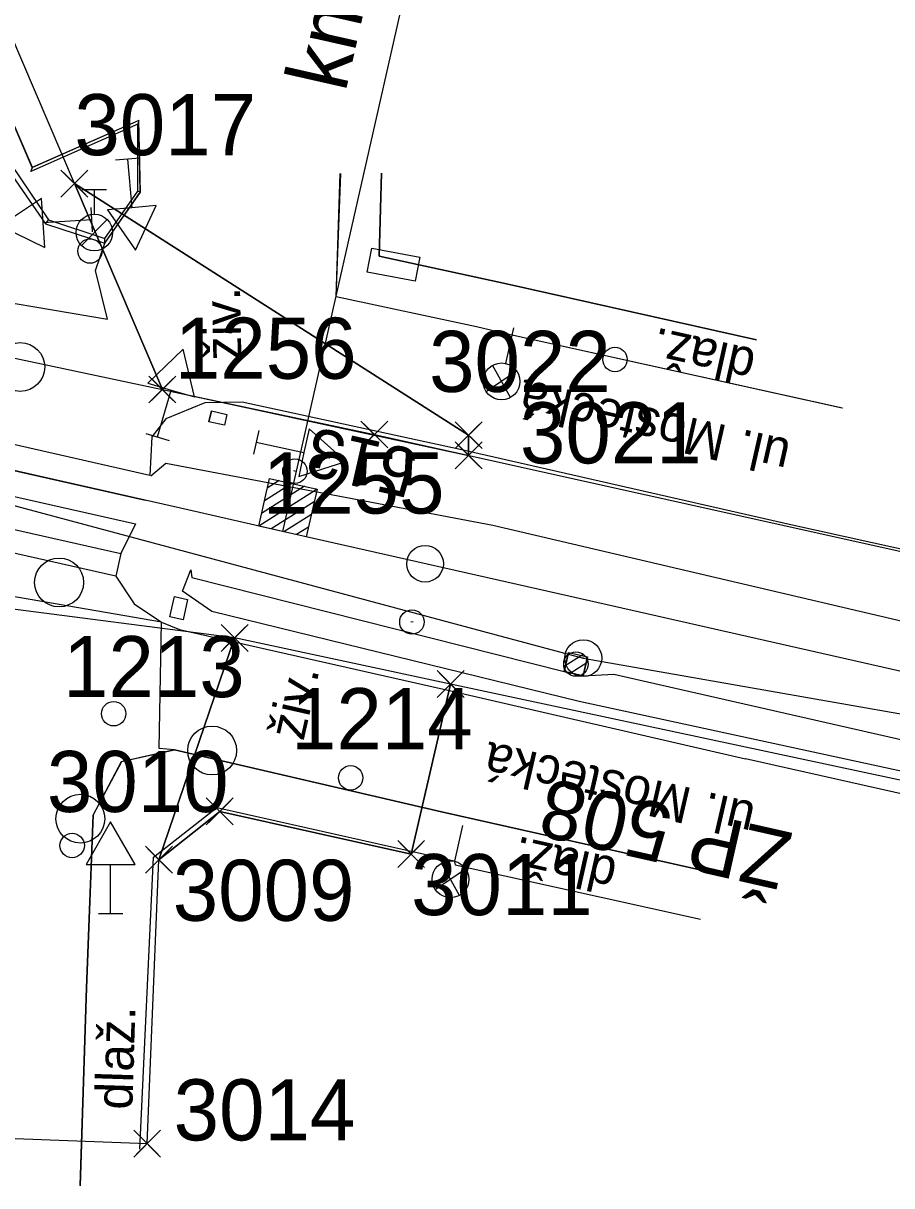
# Model space of a CAD drawing. Extents: x -738085 to -734426, y -1122197 to -1119748.
# Drawn here: x -734690.39 to -734654.84, y -1120232.59 to -1120185 of the extents above; entities that cross this region are included whole.
import ezdxf

# ---------------------------------------------------------------- set-up
doc = ezdxf.new("R2010")
doc.units = 0
for name, color, linetype in [('Dočasný zábor - do 1 roku', 7, 'Continuous'), ('SŽDC', 7, 'Continuous'), ('Vrstva 1', 7, 'Continuous'), ('Vrstva 11', 7, 'Continuous'), ('Vrstva 12', 7, 'Continuous'), ('Vrstva 16', 7, 'Continuous'), ('Vrstva 17', 7, 'Continuous'), ('Vrstva 23', 7, 'Continuous'), ('Vrstva 25', 7, 'Continuous'), ('Vrstva 27', 7, 'Continuous'), ('Vrstva 3', 7, 'Continuous'), ('Vrstva 4', 7, 'Continuous'), ('Vrstva 41', 7, 'Continuous'), ('Vrstva 43', 7, 'Continuous'), ('Vrstva 47', 7, 'Continuous'), ('Vrstva 49', 7, 'Continuous'), ('Vrstva 51', 7, 'Continuous'), ('Vrstva 60', 7, 'Continuous'), ('Vrstva 63', 7, 'Continuous'), ('Vrstva 7', 7, 'Continuous')]:
    doc.layers.add(name, color=color, linetype=linetype)

msp = doc.modelspace()

# ---------------------------------------------------------------- linework, layer by layer
at = {"layer": 'Dočasný zábor - do 1 roku'}
for p, q in [((-734688.3, -1120191.56), (-734697.213, -1120170.677)), ((-734684.7, -1120199.99), (-734688.3, -1120191.56)), ((-734688.3, -1120191.56), (-734684.7, -1120199.99)), ((-734672.163, -1120201.858), (-734688.3, -1120191.56)), ((-734700.75, -1120196.59), (-734684.7, -1120199.99)), ((-734684.7, -1120199.99), (-734672.163, -1120202.687)), ((-734672.163, -1120202.687), (-734672.163, -1120201.858)), ((-734681.74, -1120210.16), (-734699.68, -1120207.84)), ((-734684.84, -1120219.24), (-734681.74, -1120210.16)), ((-734672.9, -1120212.048), (-734681.74, -1120210.16)), ((-734681.74, -1120210.16), (-734681.74, -1120210.16)), ((-734674.515, -1120219.007), (-734672.9, -1120212.048)), ((-734685.32, -1120230.86), (-734684.84, -1120219.24)), ((-734700.26, -1120230.299), (-734685.32, -1120230.86))]:
    msp.add_line(p, q, dxfattribs=at)
for points in [[(-734688.3, -1120191.56), (-734672.163, -1120201.858), (-734672.163, -1120202.687)], [(-734681.74, -1120210.16), (-734684.84, -1120219.24), (-734682.35, -1120217.26), (-734674.515, -1120219.007)], [(-734672.9, -1120212.048), (-734674.515, -1120219.007), (-734682.35, -1120217.26), (-734684.84, -1120219.24)]]:
    msp.add_lwpolyline(points, dxfattribs=at)
at = {"layer": 'SŽDC'}
for p, q in [((-734700.75, -1120196.59), (-734684.7, -1120199.99)), ((-734684.7, -1120199.99), (-734676.02, -1120201.83)), ((-734676.02, -1120201.83), (-734595.59, -1120219.69)), ((-734681.74, -1120210.16), (-734699.68, -1120207.84))]:
    msp.add_line(p, q, dxfattribs=at)
msp.add_lwpolyline([(-734644.28, -1120218.16), (-734672.9, -1120212.048), (-734681.74, -1120210.16)], dxfattribs=at)
at = {"layer": 'Vrstva 1'}
msp.add_lwpolyline([(-734613.421, -1120220.79), (-734634.887, -1120215.956), (-734653.902, -1120211.657), (-734667.211, -1120208.647), (-734679.781, -1120205.8), (-734683.652, -1120204.918), (-734685.399, -1120204.523), (-734700.124, -1120201.196), (-734707.734, -1120199.476), (-734730.994, -1120194.203), (-734759.473, -1120187.753), (-734794.897, -1120179.749), (-734825.419, -1120172.844), (-734846.465, -1120168.091), (-734858.476, -1120165.343)], dxfattribs=at)
msp.add_lwpolyline([(-734613.421, -1120220.79), (-734634.887, -1120215.956), (-734653.902, -1120211.657), (-734667.211, -1120208.647), (-734679.781, -1120205.8), (-734683.652, -1120204.918), (-734685.399, -1120204.523), (-734700.124, -1120201.196), (-734707.734, -1120199.476), (-734730.994, -1120194.203), (-734759.473, -1120187.753), (-734794.897, -1120179.749), (-734825.419, -1120172.844), (-734846.465, -1120168.091), (-734858.476, -1120165.343)], dxfattribs=at)
at = {"layer": 'Vrstva 11'}
for p, q in [((-734667.473, -1120210.832), (-734668.256, -1120211.326)), ((-734667.279, -1120211.152), (-734668.051, -1120211.64))]:
    msp.add_line(p, q, dxfattribs=at)
msp.add_circle((-734667.769, -1120211.23), 0.5, dxfattribs=at)
at = {"layer": 'Vrstva 12'}
for p, q in [((-734682.692, -1120200.869), (-734682.792, -1120201.308)), ((-734682.058, -1120201.012), (-734682.158, -1120201.451)), ((-734667.467, -1120211.708), (-734667.291, -1120210.928))]:
    msp.add_line(p, q, dxfattribs=at)
for points in [[(-734682.158, -1120201.451), (-734682.792, -1120201.308), (-734682.692, -1120200.869), (-734682.058, -1120201.012), (-734682.158, -1120201.451)], [(-734682.692, -1120200.869), (-734682.692, -1120200.869), (-734682.058, -1120201.012), (-734682.058, -1120201.012)], [(-734684.2, -1120208.469), (-734683.664, -1120208.591), (-734683.852, -1120209.42), (-734684.389, -1120209.297), (-734684.2, -1120208.469)], [(-734668.071, -1120210.752), (-734667.291, -1120210.928), (-734667.467, -1120211.708), (-734668.248, -1120211.532), (-734668.071, -1120210.752)], [(-734668.071, -1120210.752), (-734668.248, -1120211.532), (-734668.248, -1120211.532)], [(-734668.248, -1120211.532), (-734667.467, -1120211.708), (-734667.467, -1120211.708)]]:
    msp.add_lwpolyline(points, dxfattribs=at)
at = {"layer": 'Vrstva 16'}
for p, q in [((-734690.085, -1120191.06), (-734690.021, -1120190.906)), ((-734689.481, -1120193.204), (-734689.48, -1120193.207)), ((-734689.48, -1120193.207), (-734689.361, -1120193.039)), ((-734687.051, -1120194.004), (-734687.053, -1120193.814)), ((-734687.051, -1120194.004), (-734687.051, -1120194.004))]:
    msp.add_line(p, q, dxfattribs=at)
for points in [[(-734693.983, -1120184.429), (-734693.706, -1120184.991), (-734691.09, -1120190.87), (-734689.481, -1120193.204), (-734687.051, -1120194.004), (-734685.594, -1120191.915), (-734685.657, -1120188.975), (-734690.021, -1120190.906), (-734692.007, -1120186.315), (-734692.012, -1120183.607), (-734691.887, -1120180.057), (-734691.681, -1120177.463)], [(-734693.983, -1120184.429), (-734693.673, -1120185.028), (-734691.091, -1120190.868), (-734689.48, -1120193.207), (-734687.051, -1120194.004), (-734685.605, -1120191.915), (-734685.658, -1120188.976), (-734690.023, -1120190.9), (-734692.008, -1120186.313), (-734692.012, -1120183.607)], [(-734693.983, -1120184.429), (-734693.738, -1120184.328), (-734693.487, -1120184.951), (-734690.892, -1120190.781), (-734689.361, -1120193.039), (-734687.053, -1120193.814), (-734685.709, -1120191.874), (-734685.703, -1120189.123), (-734690.085, -1120191.06)], [(-734685.657, -1120188.975), (-734685.658, -1120188.976), (-734685.703, -1120189.123)], [(-734690.021, -1120190.906), (-734690.023, -1120190.9), (-734690.085, -1120191.06)], [(-734656.869, -1120200.755), (-734670.691, -1120197.691), (-734671.842, -1120197.428), (-734677.579, -1120196.192), (-734677.39, -1120191.145)], [(-734675.732, -1120191.133), (-734675.819, -1120194.533), (-734670.613, -1120195.666), (-734660.375, -1120197.952)], [(-734685.594, -1120191.915), (-734685.605, -1120191.915), (-734685.709, -1120191.874)], [(-734662.447, -1120219.703), (-734673.267, -1120217.272), (-734684.199, -1120214.747), (-734686.375, -1120215.227), (-734687.529, -1120217.4), (-734687.799, -1120224.482), (-734688.058, -1120232.586)], [(-734685.615, -1120231.094), (-734685.057, -1120219.13), (-734682.464, -1120217.097), (-734672.751, -1120219.278), (-734672.712, -1120219.442), (-734662.672, -1120221.679)]]:
    msp.add_lwpolyline(points, dxfattribs=at)
at = {"layer": 'Vrstva 17'}
for p, q in [((-734675.819, -1120194.533), (-734675.732, -1120191.133)), ((-734670.613, -1120195.666), (-734675.819, -1120194.533)), ((-734672.712, -1120219.442), (-734662.672, -1120221.679))]:
    msp.add_line(p, q, dxfattribs=at)
at = {"layer": 'Vrstva 23'}
msp.add_line((-734660.375, -1120197.952), (-734670.613, -1120195.666), dxfattribs=at)
msp.add_lwpolyline([(-734685.615, -1120231.094), (-734685.057, -1120219.13), (-734682.464, -1120217.097), (-734672.751, -1120219.278)], dxfattribs=at)
at = {"layer": 'Vrstva 25'}
for p, q in [((-734670.644, -1120198.922), (-734670.313, -1120197.459)), ((-734670.452, -1120200.318), (-734671.18, -1120198.998)), ((-734671.438, -1120200.078), (-734670.196, -1120199.223)), ((-734672.732, -1120219.305), (-734672.401, -1120217.842)), ((-734673.526, -1120220.461), (-734672.284, -1120219.606)), ((-734672.54, -1120220.701), (-734673.268, -1120219.381))]:
    msp.add_line(p, q, dxfattribs=at)
msp.add_lwpolyline([(-734676.308, -1120195.184), (-734676.12, -1120194.202), (-734674.156, -1120194.578), (-734674.344, -1120195.56), (-734676.308, -1120195.184)], dxfattribs=at)
for centre in [(-734670.813, -1120199.657), (-734672.901, -1120220.04)]:
    msp.add_circle(centre, 0.754, dxfattribs=at)
at = {"layer": 'Vrstva 27'}
msp.add_line((-734679.222, -1120203.344), (-734679.32, -1120203.322), dxfattribs=at)
msp.add_circle((-734679.271, -1120203.333), 0.5, dxfattribs=at)
at = {"layer": 'Vrstva 3'}
for p, q in [((-734673.222, -1120176.84), (-734679.781, -1120205.8)), ((-734678.881, -1120203.953), (-734680.639, -1120205.062)), ((-734679.399, -1120203.836), (-734680.522, -1120204.544)), ((-734679.916, -1120203.719), (-734680.405, -1120204.027)), ((-734678.364, -1120204.07), (-734680.756, -1120205.579)), ((-734678.481, -1120204.587), (-734680.239, -1120205.696)), ((-734678.598, -1120205.105), (-734679.722, -1120205.813)), ((-734678.715, -1120205.622), (-734679.205, -1120205.931))]:
    msp.add_line(p, q, dxfattribs=at)
msp.add_lwpolyline([(-734678.806, -1120206.021), (-734680.756, -1120205.579), (-734680.315, -1120203.629), (-734678.364, -1120204.07)], close=True, dxfattribs=at)
at = {"layer": 'Vrstva 4'}
msp.add_line((-734700.124, -1120201.196), (-734685.399, -1120204.523), dxfattribs=at)
msp.add_lwpolyline([(-734685.169, -1120203.528), (-734684.555, -1120202.999), (-734671.173, -1120205.544), (-734644.385, -1120211.815), (-734623.222, -1120216.49), (-734603.28, -1120220.93), (-734589.054, -1120222.819), (-734581.933, -1120222.775)], dxfattribs=at)
at = {"layer": 'Vrstva 41'}
for p, q in [((-734687.984, -1120191.806), (-734686.984, -1120191.806)), ((-734687.484, -1120191.806), (-734687.484, -1120192.814)), ((-734688.015, -1120194.096), (-734686.953, -1120193.035))]:
    msp.add_line(p, q, dxfattribs=at)
msp.add_circle((-734687.484, -1120193.564), 0.75, dxfattribs=at)
at = {"layer": 'Vrstva 43'}
msp.add_lwpolyline([(-734700.082, -1120203.618), (-734686.405, -1120206.705), (-734686.606, -1120207.634), (-734700.287, -1120204.546), (-734700.082, -1120203.618)], dxfattribs=at)
for centre in [(-734690.514, -1120199.067), (-734688.927, -1120207.889), (-734682.661, -1120214.769), (-734688.057, -1120217.561)]:
    msp.add_circle(centre, 1, dxfattribs=at)
at = {"layer": 'Vrstva 47'}
for centre in [(-734687.661, -1120194.322), (-734666.17, -1120198.76), (-734686.692, -1120213.263), (-734676.991, -1120215.888), (-734688.393, -1120218.657)]:
    msp.add_circle(centre, 0.5, dxfattribs=at)
at = {"layer": 'Vrstva 49'}
for p, q in [((-734683.88, -1120208.239), (-734683.53, -1120207.371)), ((-734682.667, -1120209.084), (-734683.88, -1120208.239)), ((-734667.641, -1120212.759), (-734682.667, -1120209.084)), ((-734640.39, -1120218.667), (-734667.641, -1120212.759))]:
    msp.add_line(p, q, dxfattribs=at)
msp.add_lwpolyline([(-734683.53, -1120207.371), (-734683.499, -1120207.692), (-734668.248, -1120211.532), (-734667.467, -1120211.708), (-734666.214, -1120211.637), (-734640.018, -1120217.602), (-734614.508, -1120223.672), (-734613.724, -1120223.83), (-734612.931, -1120223.724), (-734598.542, -1120226.335), (-734585.987, -1120228.092), (-734583.653, -1120227.271)], dxfattribs=at)
at = {"layer": 'Vrstva 51'}
for p, q in [((-734685.622, -1120190.513), (-734686.618, -1120190.599)), ((-734687.554, -1120193.538), (-734687.62, -1120192.54)), ((-734687.437, -1120195.122), (-734687.051, -1120194.004)), ((-734697.93, -1120195.257), (-734686.949, -1120197.112)), ((-734686.949, -1120197.112), (-734687.437, -1120195.122)), ((-734685.38, -1120201.792), (-734684.42, -1120202.072)), ((-734680.753, -1120201.662), (-734680.965, -1120202.64)), ((-734687.318, -1120221.439), (-734686.318, -1120221.439))]:
    msp.add_line(p, q, dxfattribs=at)
for points in [[(-734698.706, -1120173.764), (-734695.23, -1120181.618), (-734693.983, -1120184.429), (-734693.706, -1120184.991), (-734691.09, -1120190.87), (-734689.481, -1120193.204), (-734687.051, -1120194.004), (-734685.594, -1120191.915), (-734685.657, -1120188.975)], [(-734685.657, -1120188.975), (-734690.021, -1120190.906), (-734692.007, -1120186.315)], [(-734686.12, -1120190.556), (-734685.947, -1120192.548), (-734686.943, -1120192.635), (-734685.795, -1120194.292), (-734684.95, -1120192.462), (-734685.947, -1120192.548)], [(-734671.842, -1120197.428), (-734677.579, -1120196.192), (-734677.414, -1120191.147)], [(-734687.587, -1120193.039), (-734689.583, -1120193.172), (-734689.649, -1120192.174), (-734691.329, -1120193.288), (-734689.516, -1120194.17), (-734689.583, -1120193.172)], [(-734658.976, -1120205.526), (-734672.503, -1120202.452), (-734681.43, -1120200.503), (-734682.967, -1120200.534), (-734684.561, -1120201.186), (-734685.13, -1120201.924), (-734685.214, -1120203.506), (-734699.559, -1120200.255), (-734700.128, -1120198.059), (-734700.649, -1120196.031), (-734698.09, -1120195.452), (-734697.927, -1120195.313), (-734697.93, -1120195.257), (-734698.04, -1120194.915)], [(-734656.85, -1120200.76), (-734670.693, -1120197.691), (-734671.842, -1120197.428)], [(-734684.9, -1120201.932), (-734684.34, -1120200.012), (-734683.38, -1120200.292), (-734683.85, -1120198.332), (-734685.3, -1120199.732), (-734684.34, -1120200.012)], [(-734680.859, -1120202.151), (-734678.904, -1120202.574), (-734679.115, -1120203.551), (-734677.194, -1120202.943), (-734678.693, -1120201.596), (-734678.904, -1120202.574)], [(-734722.773, -1120203.706), (-734710.677, -1120205.432), (-734705.214, -1120206.089), (-734701.642, -1120204.763), (-734700.144, -1120202.25), (-734685.794, -1120205.483), (-734686.405, -1120206.705), (-734686.606, -1120207.634), (-734685.856, -1120208.767), (-734684.729, -1120209.51), (-734683.999, -1120209.821), (-734673.195, -1120212.261), (-734660.828, -1120215.105)], [(-734581.836, -1120224.609), (-734581.933, -1120222.775), (-734581.75, -1120220.917), (-734582.259, -1120220.314), (-734583.293, -1120219.898), (-734588.526, -1120220.107), (-734595.069, -1120219.502), (-734615.337, -1120215.17), (-734658.976, -1120205.526)], [(-734684.2, -1120214.744), (-734684.828, -1120214.686), (-734684.729, -1120209.51), (-734696.999, -1120207.395), (-734697.066, -1120212.022)], [(-734688.059, -1120232.582), (-734687.799, -1120224.481), (-734687.528, -1120217.409), (-734686.377, -1120215.216), (-734684.2, -1120214.744), (-734673.266, -1120217.274), (-734662.445, -1120219.705)], [(-734576.137, -1120225.727), (-734581.854, -1120225.721), (-734581.624, -1120228.938), (-734582.53, -1120229.883), (-734587.309, -1120229.935), (-734598.842, -1120228.47), (-734614.658, -1120225.477), (-734640.597, -1120219.657), (-734660.828, -1120215.105)], [(-734686.818, -1120221.439), (-734686.818, -1120219.439), (-734685.818, -1120219.439), (-734686.818, -1120217.689), (-734687.818, -1120219.439), (-734686.818, -1120219.439)]]:
    msp.add_lwpolyline(points, dxfattribs=at)
at = {"layer": 'Vrstva 60'}
for p, q in [((-734687.85, -1120192.01), (-734688.85, -1120191.01)), ((-734688.75, -1120192.01), (-734687.75, -1120191.01)), ((-734687.85, -1120191.11), (-734688.85, -1120192.11)), ((-734688.75, -1120191.11), (-734687.75, -1120192.11)), ((-734688.3, -1120191.56), (-734688.3, -1120191.56)), ((-734684.25, -1120200.44), (-734685.25, -1120199.44)), ((-734684.25, -1120199.54), (-734685.25, -1120200.54)), ((-734685.15, -1120200.44), (-734684.15, -1120199.44)), ((-734685.15, -1120199.54), (-734684.15, -1120200.54)), ((-734684.7, -1120199.99), (-734684.7, -1120199.99)), ((-734675.57, -1120202.28), (-734676.57, -1120201.28)), ((-734675.57, -1120201.38), (-734676.57, -1120202.38)), ((-734676.47, -1120202.28), (-734675.47, -1120201.28)), ((-734676.47, -1120201.38), (-734675.47, -1120202.38)), ((-734671.713, -1120202.308), (-734672.713, -1120201.308)), ((-734671.713, -1120201.408), (-734672.713, -1120202.408)), ((-734672.613, -1120202.308), (-734671.613, -1120201.308)), ((-734672.613, -1120201.408), (-734671.613, -1120202.408)), ((-734676.02, -1120201.83), (-734676.02, -1120201.83)), ((-734672.163, -1120201.858), (-734672.163, -1120201.858)), ((-734671.713, -1120203.137), (-734672.713, -1120202.137)), ((-734671.713, -1120202.237), (-734672.713, -1120203.237)), ((-734672.613, -1120203.137), (-734671.613, -1120202.137)), ((-734672.613, -1120202.237), (-734671.613, -1120203.237)), ((-734672.163, -1120202.687), (-734672.163, -1120202.687)), ((-734681.29, -1120210.61), (-734682.29, -1120209.61)), ((-734682.19, -1120210.61), (-734681.19, -1120209.61)), ((-734681.29, -1120209.71), (-734682.29, -1120210.71)), ((-734682.19, -1120209.71), (-734681.19, -1120210.71)), ((-734681.74, -1120210.16), (-734681.74, -1120210.16)), ((-734672.45, -1120212.498), (-734673.45, -1120211.498)), ((-734673.35, -1120212.498), (-734672.35, -1120211.498)), ((-734672.45, -1120211.598), (-734673.45, -1120212.598)), ((-734673.35, -1120211.598), (-734672.35, -1120212.598)), ((-734672.9, -1120212.048), (-734672.9, -1120212.048)), ((-734681.9, -1120217.71), (-734682.9, -1120216.71)), ((-734682.8, -1120217.71), (-734681.8, -1120216.71)), ((-734681.9, -1120216.81), (-734682.9, -1120217.81)), ((-734682.8, -1120216.81), (-734681.8, -1120217.81)), ((-734682.35, -1120217.26), (-734682.35, -1120217.26)), ((-734684.39, -1120219.69), (-734685.39, -1120218.69)), ((-734685.29, -1120219.69), (-734684.29, -1120218.69)), ((-734674.065, -1120219.457), (-734675.065, -1120218.457)), ((-734674.065, -1120218.557), (-734675.065, -1120219.557)), ((-734674.965, -1120219.457), (-734673.965, -1120218.457)), ((-734674.965, -1120218.557), (-734673.965, -1120219.557)), ((-734684.39, -1120218.79), (-734685.39, -1120219.79)), ((-734685.29, -1120218.79), (-734684.29, -1120219.79)), ((-734674.515, -1120219.007), (-734674.515, -1120219.007)), ((-734684.84, -1120219.24), (-734684.84, -1120219.24)), ((-734684.87, -1120231.31), (-734685.87, -1120230.31)), ((-734684.87, -1120230.41), (-734685.87, -1120231.41)), ((-734685.77, -1120231.31), (-734684.77, -1120230.31)), ((-734685.77, -1120230.41), (-734684.77, -1120231.41)), ((-734685.32, -1120230.86), (-734685.32, -1120230.86))]:
    msp.add_line(p, q, dxfattribs=at)
at = {"layer": 'Vrstva 63'}
for p, q in [((-734784.587, -1120179.58), (-734667.467, -1120210.987)), ((-734667.418, -1120210.998), (-734667.516, -1120210.976)), ((-734667.467, -1120210.987), (-734562.448, -1120229.372))]:
    msp.add_line(p, q, dxfattribs=at)
msp.add_circle((-734667.467, -1120210.987), 0.756, dxfattribs=at)
at = {"layer": 'Vrstva 7'}
msp.add_line((-734674.434, -1120209.518), (-734674.532, -1120209.496), dxfattribs=at)
for centre, radius in [((-734673.943, -1120207.122), 0.75), ((-734673.943, -1120207.122), 0.75), ((-734674.483, -1120209.507), 0.5)]:
    msp.add_circle(centre, radius, dxfattribs=at)

# ---------------------------------------------------------------- texts
at = {"layer": 'Vrstva 16'}
for rotation, p in [(167.501, (-734660.342, -1120198.358)), (167.3373, (-734666.015, -1120219.194)), (88.1695, (-734685.934, -1120229.486))]:
    msp.add_text('dlaž.', height=1.5, rotation=rotation, dxfattribs=at).set_placement(p)
at = {"layer": 'Vrstva 27'}
msp.add_text('513', height=2, rotation=167.2383, dxfattribs=at).set_placement((-734674.16, -1120202.5))
at = {"layer": 'Vrstva 3'}
msp.add_text('km 0,706', height=2.5, rotation=77.2383, dxfattribs=at).set_placement((-734677.207, -1120187.86))
at = {"layer": 'Vrstva 51'}
for s, rotation, p in [('živ.', 91.1555, (-734681.46, -1120198.792)), ('ul. Mostecká', 167.197, (-734658.903, -1120202.071)), ('živ.', 77.2737, (-734678.925, -1120214.409)), ('ul. Mostecká', 167.049, (-734660.345, -1120216.926))]:
    msp.add_text(s, height=1.5, rotation=rotation, dxfattribs=at).set_placement(p)
at = {"layer": 'Vrstva 60'}
for s, p in [('3017', (-734688.3, -1120190.397)), ('1256', (-734684.185, -1120199.549)), ('3022', (-734673.779, -1120200.089)), ('3021', (-734670.059, -1120203.014)), ('1255', (-734680.586, -1120205.067)), ('1213', (-734688.765, -1120212.583)), ('1214', (-734679.433, -1120214.716)), ('3010', (-734689.426, -1120217.286)), ('3011', (-734674.515, -1120221.507)), ('3009', (-734684.273, -1120221.74)), ('3014', (-734684.238, -1120230.729))]:
    msp.add_text(s, height=2.5, dxfattribs=at).set_placement(p)
at = {"layer": 'Vrstva 63'}
msp.add_text('ŽP 508', height=2.4, rotation=167.2562, dxfattribs=at).set_placement((-734658.816, -1120218.163))

doc.saveas('drawing.dxf')
